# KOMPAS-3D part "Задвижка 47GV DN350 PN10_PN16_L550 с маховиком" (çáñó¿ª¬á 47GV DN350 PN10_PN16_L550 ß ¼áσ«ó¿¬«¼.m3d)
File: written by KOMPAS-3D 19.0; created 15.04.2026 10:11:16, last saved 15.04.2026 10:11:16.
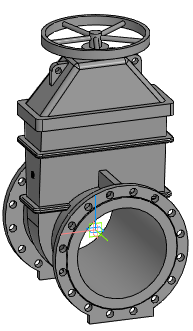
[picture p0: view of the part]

Document properties: Автор: Евгений; Полное имя файла: Z:\3.Личные\kachalov\3d для проектировщиков\2.1 Тип 47GV, 47GV.Z\Задвижка 47GV_DN40-DN600\stp_Задвижка 47GV\Задвижка 47GV DN350 PN10_PN16_L550 с маховиком.m3d

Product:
- Part/product: Задвижка 47GV DN350 PN10_PN16_L550 с маховиком

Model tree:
1. Операция без истории:1  (labels: Задвижка 47GV DN350 PN10_PN16_L550 с маховиком)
